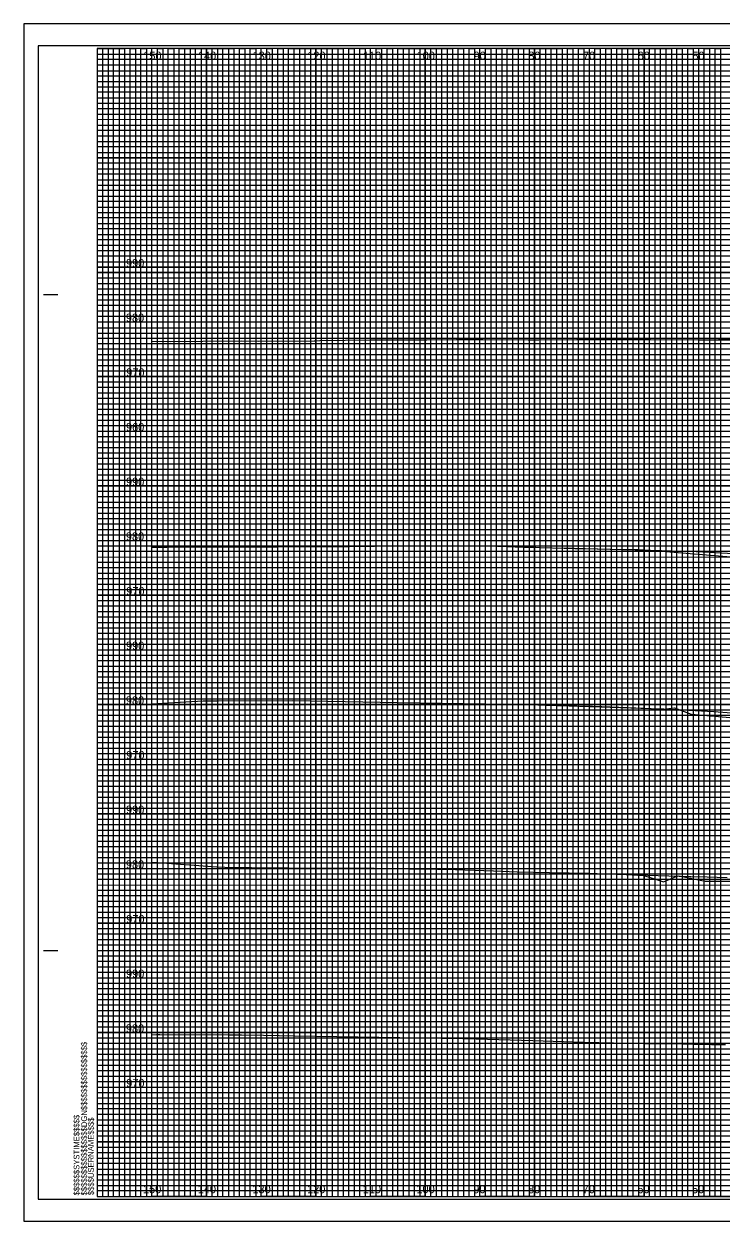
# Model space of a CAD drawing. Extents: x -13 to 760, y -5 to 1491.
# Drawn here: x -13.4 to 114.1, y -4.5 to 214.5 of the extents above; entities that cross this region are included whole.
import ezdxf

# ---------------------------------------------------------------- set-up
doc = ezdxf.new("R2010")
doc.units = 0
for name, color, linetype in [('Default', 7, 'Continuous'), ('Exist XS Ground Line', 7, 'Continuous'), ('Prop XS Elevation Labels', 7, 'Continuous'), ('Prop XS Offset Labels', 7, 'Continuous'), ('Sheet Cross Section CELL', 7, 'Continuous'), ('Sheet Cross Section Grid Major CELL', 7, 'Continuous'), ('Sheet Cross Section Grid Middle CELL', 7, 'Continuous'), ('Sheet Cross Section Grid Minor 1 CELL', 7, 'Continuous'), ('Sheet Cross Section Grid Minor 2 CELL', 7, 'Continuous'), ('Sheet Cutting Line CELL', 7, 'Continuous'), ('Sheet DOT Grid CELL', 7, 'Continuous'), ('Sheet Plot Border Inside CELL', 7, 'Continuous'), ('Sheet Plot Border Outside CELL', 7, 'Continuous')]:
    doc.layers.add(name, color=color, linetype=linetype)

msp = doc.modelspace()

# ---------------------------------------------------------------- linework, layer by layer
at = {"layer": 'Exist XS Ground Line'}
for points in [[(10, 156.49), (13.37, 156.41), (19.33, 156.45), (26.46, 156.5), (29.57, 156.49), (39.69, 156.55), (39.8, 156.55), (40.73, 156.57), (50.04, 156.69), (52.63, 156.69), (60.27, 156.72), (65.72, 156.75), (70.51, 156.77), (78.8, 156.73), (80.74, 156.74), (87.71, 156.77), (90.98, 156.78), (91.89, 156.78), (101.21, 156.77), (110.13, 156.74), (117.11, 156.83)], [(10, 156.49), (13.37, 156.41), (19.33, 156.45), (26.46, 156.5), (29.57, 156.49), (39.69, 156.55), (39.8, 156.55), (40.73, 156.57), (50.04, 156.69), (52.63, 156.69), (60.27, 156.72), (65.72, 156.75), (70.51, 156.77), (78.8, 156.73), (80.74, 156.74), (87.71, 156.77), (90.39, 156.78), (91, 156.78), (93.83, 156.77), (110.19, 156.72), (118.68, 156.73)], [(10, 118.8), (16.26, 118.89), (19.99, 118.87), (25.8, 118.85), (30.22, 118.86), (38.88, 118.89), (40.46, 118.88), (46.12, 118.9), (50.69, 118.94), (58.28, 119.04), (61.73, 119), (62.57, 119.03), (63.74, 119.04), (66.05, 119.06), (68.49, 119.05), (70.64, 119), (71.64, 119), (78.02, 118.79), (78.09, 118.78), (78.27, 118.78), (79.3, 118.77), (80.23, 118.76), (81.07, 118.75), (85.42, 118.61), (86.35, 118.59), (87.17, 118.57), (87.33, 118.56), (87.89, 118.55), (88.39, 118.53), (88.84, 118.53), (96.54, 118.35), (96.76, 118.35), (98.41, 118.31), (99.21, 118.3), (105.13, 118.11), (108.83, 118.04), (108.92, 118.04), (109, 118.03), (109.12, 118.03), (109.26, 118.03), (109.4, 118.02), (109.55, 118.01), (109.66, 118), (117.54, 117.59)], [(10, 118.8), (12.71, 118.79), (19.99, 118.87), (25.8, 118.85), (30.22, 118.86), (33.07, 118.84), (40.46, 118.88), (46.12, 118.9), (50.69, 118.94), (58.28, 119.04), (61.73, 119), (62.57, 119.03), (63.74, 119.04), (66.05, 119.06), (68.49, 119.05), (70.64, 119), (71.64, 119), (78.02, 118.79), (78.09, 118.78), (78.27, 118.78), (79.3, 118.77), (80.23, 118.76), (81.07, 118.75), (85.42, 118.61), (86.35, 118.59), (87.17, 118.57), (87.33, 118.56), (87.89, 118.55), (88.39, 118.53), (88.84, 118.53), (89.22, 118.52), (96.15, 118.36), (96.55, 118.35), (96.81, 118.35), (97.1, 118.35), (97.34, 118.35), (98.94, 118.38), (102.5, 118.14), (116.61, 116.96)], [(10, 90.13), (11.99, 90.24), (19.35, 90.65), (21.91, 90.67), (22.15, 90.67), (35.7, 90.73), (54.96, 90.36), (79.06, 90.02), (82.06, 89.9), (90.56, 89.71), (92.29, 89.65), (98.5, 89.4), (102.53, 89.22), (103.65, 89.18), (112.76, 88.69), (118.43, 88.31)], [(10, 90.13), (11.99, 90.24), (19.35, 90.65), (21.91, 90.67), (22.15, 90.67), (35.7, 90.73), (54.96, 90.36), (79.06, 90.02), (82.06, 89.9), (86.28, 89.73), (101.32, 89.29), (102.72, 89.16), (103.35, 89.1), (103.96, 89.22), (105.6, 89.4), (108.62, 88.23), (120.67, 87.18)], [(10, 61.13), (11.07, 61.09), (21.88, 60.32), (23.31, 60.24), (28.2, 60.17), (41.78, 60.06), (50.65, 60.03), (52.01, 60.02), (56.91, 59.96), (62.25, 59.89), (63.73, 59.86), (72.48, 59.55), (76.82, 59.38), (82.72, 59.24), (89.9, 59.12), (92.95, 59.04), (94.91, 58.98), (108.38, 58.56), (108.57, 58.56), (111.52, 58.45), (115.21, 58.37)], [(10, 61.13), (11.07, 61.09), (21.88, 60.32), (23.31, 60.24), (28.2, 60.17), (41.78, 60.06), (50.65, 60.03), (52.01, 60.02), (56.91, 59.96), (62.25, 59.89), (63.73, 59.86), (72.48, 59.55), (76.82, 59.38), (82.72, 59.24), (89.9, 59.12), (92.95, 59.04), (95.67, 58.96), (99.89, 58.72), (100.96, 58.39), (103.56, 57.54), (105.87, 58.51), (106.35, 58.65), (111.2, 57.68), (112.53, 57.68), (123.14, 57.7)], [(10, 29.58), (10.83, 29.61), (10.89, 29.62), (11.43, 29.63), (24.02, 29.59), (26.41, 29.58), (30.43, 29.52), (36.13, 29.41), (66.85, 28.91), (67.02, 28.9), (67.21, 28.9), (79.68, 28.52), (89, 28.22), (99.93, 27.99), (102.11, 27.98), (102.93, 27.98), (104.35, 27.96), (106.92, 27.92), (106.96, 27.92), (107.22, 27.91), (109.15, 27.88), (109.78, 27.87), (111.28, 27.84), (112.33, 27.82), (114.06, 27.8), (114.87, 27.78)]]:
    msp.add_lwpolyline(points, dxfattribs=at)
at = {"layer": 'Sheet Cross Section CELL'}
for p, q in [((-9.8, 165), (-7.3, 165)), ((-9.7, 165), (-7.2, 165)), ((-9.8, 45), (-7.3, 45)), ((-9.7, 45), (-7.2, 45)), ((0, 0), (0, 0)), ((0, 0), (0, 0)), ((0, 0), (0, 0)), ((0, 0), (0, 0)), ((0, 0), (0, 0)), ((0, 0), (0, 0)), ((0, 0), (0, 0))]:
    msp.add_line(p, q, dxfattribs=at)
msp.add_lwpolyline([(320, 210), (0, 210), (0, 0), (320, 0)], close=True, dxfattribs=at)
at = {"layer": 'Sheet Cross Section Grid Major CELL'}
for p, q in [((10, 210), (0, 210)), ((10, 0), (10, 210)), ((30, 210), (20, 210)), ((20, 210), (20, 0)), ((30, 0), (30, 210)), ((50, 210), (40, 210)), ((40, 210), (40, 0)), ((50, 0), (50, 210)), ((70, 210), (60, 210)), ((60, 210), (60, 0)), ((70, 0), (70, 210)), ((90, 210), (80, 210)), ((80, 210), (80, 0)), ((90, 0), (90, 210)), ((110, 210), (100, 210)), ((100, 210), (100, 0)), ((110, 0), (110, 210)), ((20, 0), (10, 0)), ((40, 0), (30, 0)), ((60, 0), (50, 0)), ((80, 0), (70, 0)), ((100, 0), (90, 0)), ((120, 0), (110, 0))]:
    msp.add_line(p, q, dxfattribs=at)
for points in [[(0, 200), (320, 200), (320, 190), (0, 190)], [(0, 180), (320, 180), (320, 170), (0, 170)], [(0, 160), (320, 160), (320, 150), (0, 150)], [(0, 140), (320, 140), (320, 130), (0, 130)], [(0, 120), (320, 120), (320, 110), (0, 110)], [(0, 100), (320, 100), (320, 90), (0, 90)], [(0, 80), (320, 80), (320, 70), (0, 70)], [(0, 60), (320, 60), (320, 50), (0, 50)], [(0, 40), (320, 40), (320, 30), (0, 30)], [(0, 20), (320, 20), (320, 10), (0, 10)]]:
    msp.add_lwpolyline(points, dxfattribs=at)
at = {"layer": 'Sheet Cross Section Grid Middle CELL'}
for points in [[(0, 210), (5, 210), (5, 0), (15, 0), (15, 210), (25, 210), (25, 0), (35, 0), (35, 210), (45, 210), (45, 0), (55, 0), (55, 210), (65, 210), (65, 0), (75, 0), (75, 210), (85, 210), (85, 0), (95, 0), (95, 210), (105, 210), (105, 0), (115, 0)], [(0, 205), (275, 205)], [(0, 185), (320, 185), (320, 195), (0, 195)], [(0, 165), (320, 165), (320, 175), (0, 175)], [(0, 145), (320, 145), (320, 155), (0, 155)], [(0, 125), (320, 125), (320, 135), (0, 135)], [(0, 105), (320, 105), (320, 115), (0, 115)], [(0, 85), (320, 85), (320, 95), (0, 95)], [(0, 65), (320, 65), (320, 75), (0, 75)], [(0, 45), (320, 45), (320, 55), (0, 55)], [(0, 25), (320, 25), (320, 35), (0, 35)], [(0, 5), (320, 5), (320, 15), (0, 15)]]:
    msp.add_lwpolyline(points, dxfattribs=at)
at = {"layer": 'Sheet Cross Section Grid Minor 1 CELL'}
for p, q in [((0, 209), (260, 209)), ((260, 207.98), (0, 207.98)), ((0, 207.98), (0, 207)), ((0, 207), (260, 207)), ((260, 205.89), (0, 205.89)), ((0, 205.89), (0, 204)), ((0, 204), (320, 204))]:
    msp.add_line(p, q, dxfattribs=at)
for points in [[(0, 203), (270, 203), (320, 203), (320, 202), (0, 202)], [(0, 201), (320, 201), (320, 199), (0, 199)], [(0, 198), (320, 198), (320, 197), (0, 196.98)], [(0, 196), (320, 196), (320, 194), (0, 194)], [(0, 193), (320, 193), (320, 192), (0, 192)], [(0, 191), (320, 191), (320, 189), (0, 189)], [(0, 188), (320, 188), (320, 187), (0, 187)], [(0, 186), (320, 186), (320, 184), (0, 184)], [(0, 183), (320, 183), (320, 182), (0, 182)], [(0, 181), (320, 181), (320, 179), (0, 179)], [(0, 178), (320, 178), (320, 177), (0, 177)], [(0, 176), (320, 176), (320, 173.95), (320, 173), (320, 172), (0, 172)], [(0, 174), (320, 174), (320, 173), (0, 173)], [(0, 171), (320, 171), (320, 169), (0, 169.03)], [(0, 169.03), (320, 169), (320, 168), (0, 168)], [(0, 167), (320, 167), (320, 166), (0, 166)], [(0, 164), (320, 164), (320, 163), (0, 163)], [(0, 162), (320, 162), (320, 161), (0, 161)], [(-0.07, 158.89), (320, 158.89), (320, 157.88), (-0.07, 157.88)], [(0, 157), (320, 157), (320, 156), (0, 156)], [(0, 154), (320, 154), (320, 153), (0, 153)], [(0, 152), (320, 152), (320, 151), (0, 151)], [(0, 149), (320, 149), (320, 148), (0, 148)], [(0, 147), (320, 147), (320, 146), (0, 146)], [(0, 144), (320, 144), (320, 143), (0, 143)], [(0, 142), (320, 142), (320, 141), (0, 141)], [(0, 139), (320, 139), (319.99, 137.98), (0, 138)], [(0, 137), (320, 137), (320, 136), (0, 136)], [(0, 134), (320, 134), (320, 133), (0, 133)], [(0, 132), (320, 132), (320, 131), (0, 131)], [(0, 129), (320, 129), (320, 128), (0, 128)], [(0, 127), (320, 127), (320, 126), (0, 126)], [(0, 124), (320, 124), (320, 123), (0, 123)], [(0, 122), (320, 122), (320, 121), (0, 121)], [(0, 119), (320, 119), (320, 118), (0, 118)], [(0, 116.99), (320.07, 116.91), (320, 116), (0, 116)], [(0, 114), (320, 114), (320, 113), (0, 113)], [(0, 112), (320, 112), (320, 111), (0, 111)], [(0, 109), (320, 109), (320, 108), (0, 108)], [(0, 107), (320, 107), (320, 106), (0, 106)], [(0, 104), (320, 104), (320, 103), (0, 103)], [(0, 102), (320, 102), (320, 101), (0, 101)], [(0, 99), (320, 99), (320, 98), (0, 98)], [(0, 97), (320, 97), (320, 96), (0, 96)], [(0, 94), (320, 94), (320, 93), (0, 93)], [(0, 92), (320, 92), (320, 91), (0, 91)], [(0, 89), (320, 89), (320, 88), (0, 88)], [(0, 87), (320, 87), (320, 86), (0, 86)], [(0, 84), (320, 84), (320, 83), (0, 83)], [(0, 82), (320, 82), (320, 81), (0, 81)], [(0, 79), (320, 79), (319.99, 77.98), (0, 78)], [(0, 77), (320, 77), (320, 76), (0, 76)], [(0, 74), (320, 74), (320, 73), (0, 73)], [(0, 72), (320, 72), (320, 71), (0, 71)], [(0, 69), (320, 69), (320, 68), (0, 68)], [(0, 67), (320, 67), (320, 66), (0, 66)], [(0, 64), (320, 64), (320, 63), (0, 63)], [(0, 62), (320, 62), (320, 61), (0, 61)], [(0, 59), (320, 59), (320, 58), (0, 58)], [(0, 56.99), (320.07, 56.91), (320, 56), (0, 56)], [(0, 54), (320, 54), (320, 53), (0, 53)], [(0, 52), (320, 52), (320, 51), (0, 51)], [(0, 49), (320, 49), (320, 48), (0, 48)], [(0, 47), (320, 47), (320, 46), (0, 46)], [(0, 44), (320, 44), (320, 43), (0, 43)], [(0, 42), (320, 42), (320, 41), (0, 41)], [(0, 39), (320, 39), (320, 38), (0, 38)], [(0, 37), (320, 37), (320, 36), (0, 36)], [(0, 34), (320, 34), (320, 33), (0, 33)], [(0, 32), (320, 32), (320, 31), (0, 31)], [(0, 29), (320, 29), (320, 28), (0, 28)], [(0, 27), (320, 27), (320, 26), (0, 26)], [(0, 24), (320, 24), (320, 23), (0, 23)], [(0, 22), (320, 22), (320, 21), (0, 21)], [(0, 19), (320, 19), (320, 18), (0, 18)], [(0, 17), (320, 17), (320, 16), (0, 16)], [(0, 14), (320, 14), (320, 13), (0, 13)], [(0, 12), (320, 12), (320, 11), (0, 11)], [(0, 9), (320, 9), (320, 8), (0, 8)], [(0, 7), (320, 7), (320, 6), (0, 6)], [(0, 4), (320, 4), (320, 3), (0, 3)], [(0, 2), (320, 2), (320, 1), (0, 1)]]:
    msp.add_lwpolyline(points, dxfattribs=at)
at = {"layer": 'Sheet Cross Section Grid Minor 2 CELL'}
for points in [[(0, 0), (1, 0), (1, 210), (2, 210), (2, 0)], [(2, 0), (3, 0), (3, 210), (4, 210), (4, 0)], [(5, 0), (6, 0), (6, 210), (7, 210), (7, 0)], [(7, 0), (8, 0), (8, 210), (9, 210), (9, 0)], [(10, 0), (11, 0), (11, 210), (12, 210), (12, 0)], [(12, 0), (13, 0), (13, 210), (14, 210), (14, 0)], [(15, 0), (16, 0), (16, 210), (17, 210), (17, 0)], [(17, 0), (18, 0), (18, 210), (19, 210), (19, 0)], [(20, 0), (21, 0), (21, 210), (22, 210), (22, 0)], [(22, 0), (23, 0), (23, 210), (24, 210), (24, 0)], [(25, 0), (26, 0), (26, 210), (27, 210), (27, 0)], [(27, 0), (28, 0), (28, 210), (29, 210), (29, 0)], [(30, 0), (31, 0), (31, 210), (32, 210), (32, 0)], [(32, 0), (33, 0), (33, 210), (34, 210), (34, 0)], [(35, 0), (36, 0), (36, 210), (37, 210), (37, 0)], [(37, 0), (38, 0), (38, 210), (39, 210), (39, 0)], [(40, 0), (41, 0), (41, 210), (42, 210), (42, 0)], [(42, 0), (43, 0), (43, 210), (44, 210), (44, 0)], [(45, 0), (46, 0), (46, 210), (47, 210), (47, 0)], [(47, 0), (48, 0), (48, 210), (49, 210), (49, 0)], [(50, 0), (51, 0), (51, 210), (52, 210), (52, 0)], [(52, 0), (53, 0), (53, 210), (54, 210), (54, 0)], [(55, 0), (56, 0), (56, 210), (57, 210), (57, 0)], [(57, 0), (58, 0), (58, 210), (59, 210), (59, 0)], [(60, 0), (61, 0), (61, 210), (62, 210), (62, 0)], [(62, 0), (63, 0), (63, 210), (64, 210), (64, 0)], [(65, 0), (66, 0), (66, 210), (67, 210), (67, 0)], [(67, 0), (68, 0), (68, 210), (69, 210), (69, 0)], [(70, 0), (71, 0), (71, 210), (72, 210), (72, 0)], [(72, 0), (73, 0), (73, 210), (74, 210), (74, 0)], [(75, 0), (76, 0), (76, 210), (77, 210), (77, 0)], [(77, 0), (78, 0), (78, 210), (79, 210), (79, 0)], [(80, 0), (81, 0), (81, 210), (82, 210), (82, 0)], [(82, 0), (83, 0), (83, 210), (84, 210), (84, 0)], [(85, 0), (86, 0), (86, 210), (87, 210), (87, 0)], [(87, 0), (88, 0), (88, 210), (89, 210), (89, 0)], [(90, 0), (91, 0), (91, 210), (92, 210), (92, 0)], [(92, 0), (93, 0), (93, 210), (94, 210), (94, 0)], [(95, 0), (96, 0), (96, 210), (97, 210), (97, 0)], [(97, 0), (98, 0), (98, 210), (99, 210), (99, 0)], [(100, 0), (101, 0), (101, 210), (102, 210), (102, 0)], [(102, 0), (103, 0), (103, 210), (104, 210), (104, 0)], [(105, 0), (106, 0), (106, 210), (107, 210), (107, 0)], [(107, 0), (108, 0), (108, 210), (109, 210), (109, 0)], [(110, 0), (111, 0), (111, 210), (112, 210), (112, 0)], [(112, 0), (113, 0), (113, 210), (114, 210), (114, 0)]]:
    msp.add_lwpolyline(points, dxfattribs=at)
at = {"layer": 'Sheet Cutting Line CELL'}
for p, q in [((323.3, 214.5), (-13.4, 214.5)), ((-13.4, 214.5), (-13.4, -4.5)), ((-13.4, -4.5), (323.3, -4.5))]:
    msp.add_line(p, q, dxfattribs=at)
at = {"layer": 'Sheet DOT Grid CELL'}
for p, q in [((10, 0), (10, 210)), ((20, 0), (20, 210)), ((30, 0), (30, 210)), ((40, 0), (40, 210)), ((50, 0), (50, 210)), ((60, 0), (60, 210)), ((70, 0), (70, 210)), ((80, 0), (80, 210)), ((90, 0), (90, 210)), ((100, 0), (100, 210)), ((110, 0), (110, 210)), ((0, 200), (320, 200)), ((0, 190), (320, 190)), ((0, 180), (320, 180)), ((0, 170), (320, 170)), ((0, 160), (320, 160)), ((0, 150), (320, 150)), ((0, 140), (320, 140)), ((0, 130), (320, 130)), ((0, 120), (320, 120)), ((0, 110), (320, 110)), ((0, 100), (320, 100)), ((0, 90), (320, 90)), ((0, 80), (320, 80)), ((0, 70), (320, 70)), ((0, 60), (320, 60)), ((0, 50), (320, 50)), ((0, 40), (320, 40)), ((0, 30), (320, 30)), ((0, 20), (320, 20)), ((0, 10), (320, 10))]:
    msp.add_line(p, q, dxfattribs=at)
at = {"layer": 'Sheet Plot Border Inside CELL'}
msp.add_lwpolyline([(-10.8, -0.5), (322.4, -0.5), (322.4, 210.5), (-10.8, 210.5)], close=True, dxfattribs=at)
at = {"layer": 'Sheet Plot Border Outside CELL'}
msp.add_lwpolyline([(-13.4, -4.5), (323.3, -4.5), (323.3, 214.5), (-13.4, 214.5)], close=True, dxfattribs=at)

# ---------------------------------------------------------------- texts
at = {"layer": 'Default'}
for p in [(10, 140), (10, 110), (10, 80), (10, 50), (10, 20)]:
    msp.add_text('-', height=0.0001, dxfattribs=at).set_placement(p)
at = {"layer": 'Prop XS Elevation Labels'}
for s, p in [('990', (5.26, 170)), ('980', (5.24, 160)), ('970', (5.3, 150)), ('960', (5.26, 140)), ('990', (5.26, 130)), ('980', (5.24, 120)), ('970', (5.3, 110)), ('990', (5.26, 100)), ('980', (5.24, 90)), ('970', (5.3, 80)), ('990', (5.26, 70)), ('980', (5.24, 60)), ('970', (5.3, 50)), ('990', (5.26, 40)), ('980', (5.24, 30)), ('970', (5.3, 20))]:
    msp.add_text(s, height=1.5, dxfattribs=at).set_placement(p)
at = {"layer": 'Prop XS Offset Labels'}
for s, p in [('150', (8.41, 207.93)), ('140', (18.41, 207.93)), ('130', (28.41, 207.93)), ('120', (38.41, 207.93)), ('110', (48.59, 207.93)), ('100', (58.41, 207.93)), ('90', (68.83, 207.93)), ('80', (78.83, 207.93)), ('70', (88.83, 207.93)), ('60', (98.83, 207.93)), ('50', (108.83, 207.93)), ('150', (8.37, 0.59)), ('140', (18.37, 0.59)), ('130', (28.37, 0.59)), ('120', (38.37, 0.59)), ('110', (48.55, 0.59)), ('100', (58.37, 0.59)), ('90', (68.78, 0.59)), ('80', (78.78, 0.59)), ('70', (88.78, 0.59)), ('60', (98.78, 0.59)), ('50', (108.78, 0.59))]:
    msp.add_text(s, height=1.5, dxfattribs=at).set_placement(p)
at = {"layer": 'Sheet Cross Section CELL'}
for s, p in [('$$$$$$$$$$$$$$$$DGN$$$$$$$$$$$$$$$$', (-1.88, 0.18)), ('$$$$$$SYSTIME$$$$$', (-3.26, 0.18)), ('$$$$USERNAME$$$$', (-0.62, 0.23))]:
    msp.add_text(s, height=1.05, rotation=90, dxfattribs=at).set_placement(p)

doc.saveas('drawing.dxf')
